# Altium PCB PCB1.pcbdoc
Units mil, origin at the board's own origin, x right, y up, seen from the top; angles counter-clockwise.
Board outline 4550 x 4255 mil, 4 copper layers (Top Layer, Inner1, Inner2, Bottom Layer); 26 components, 17 nets, 63 pads, 18 vias.
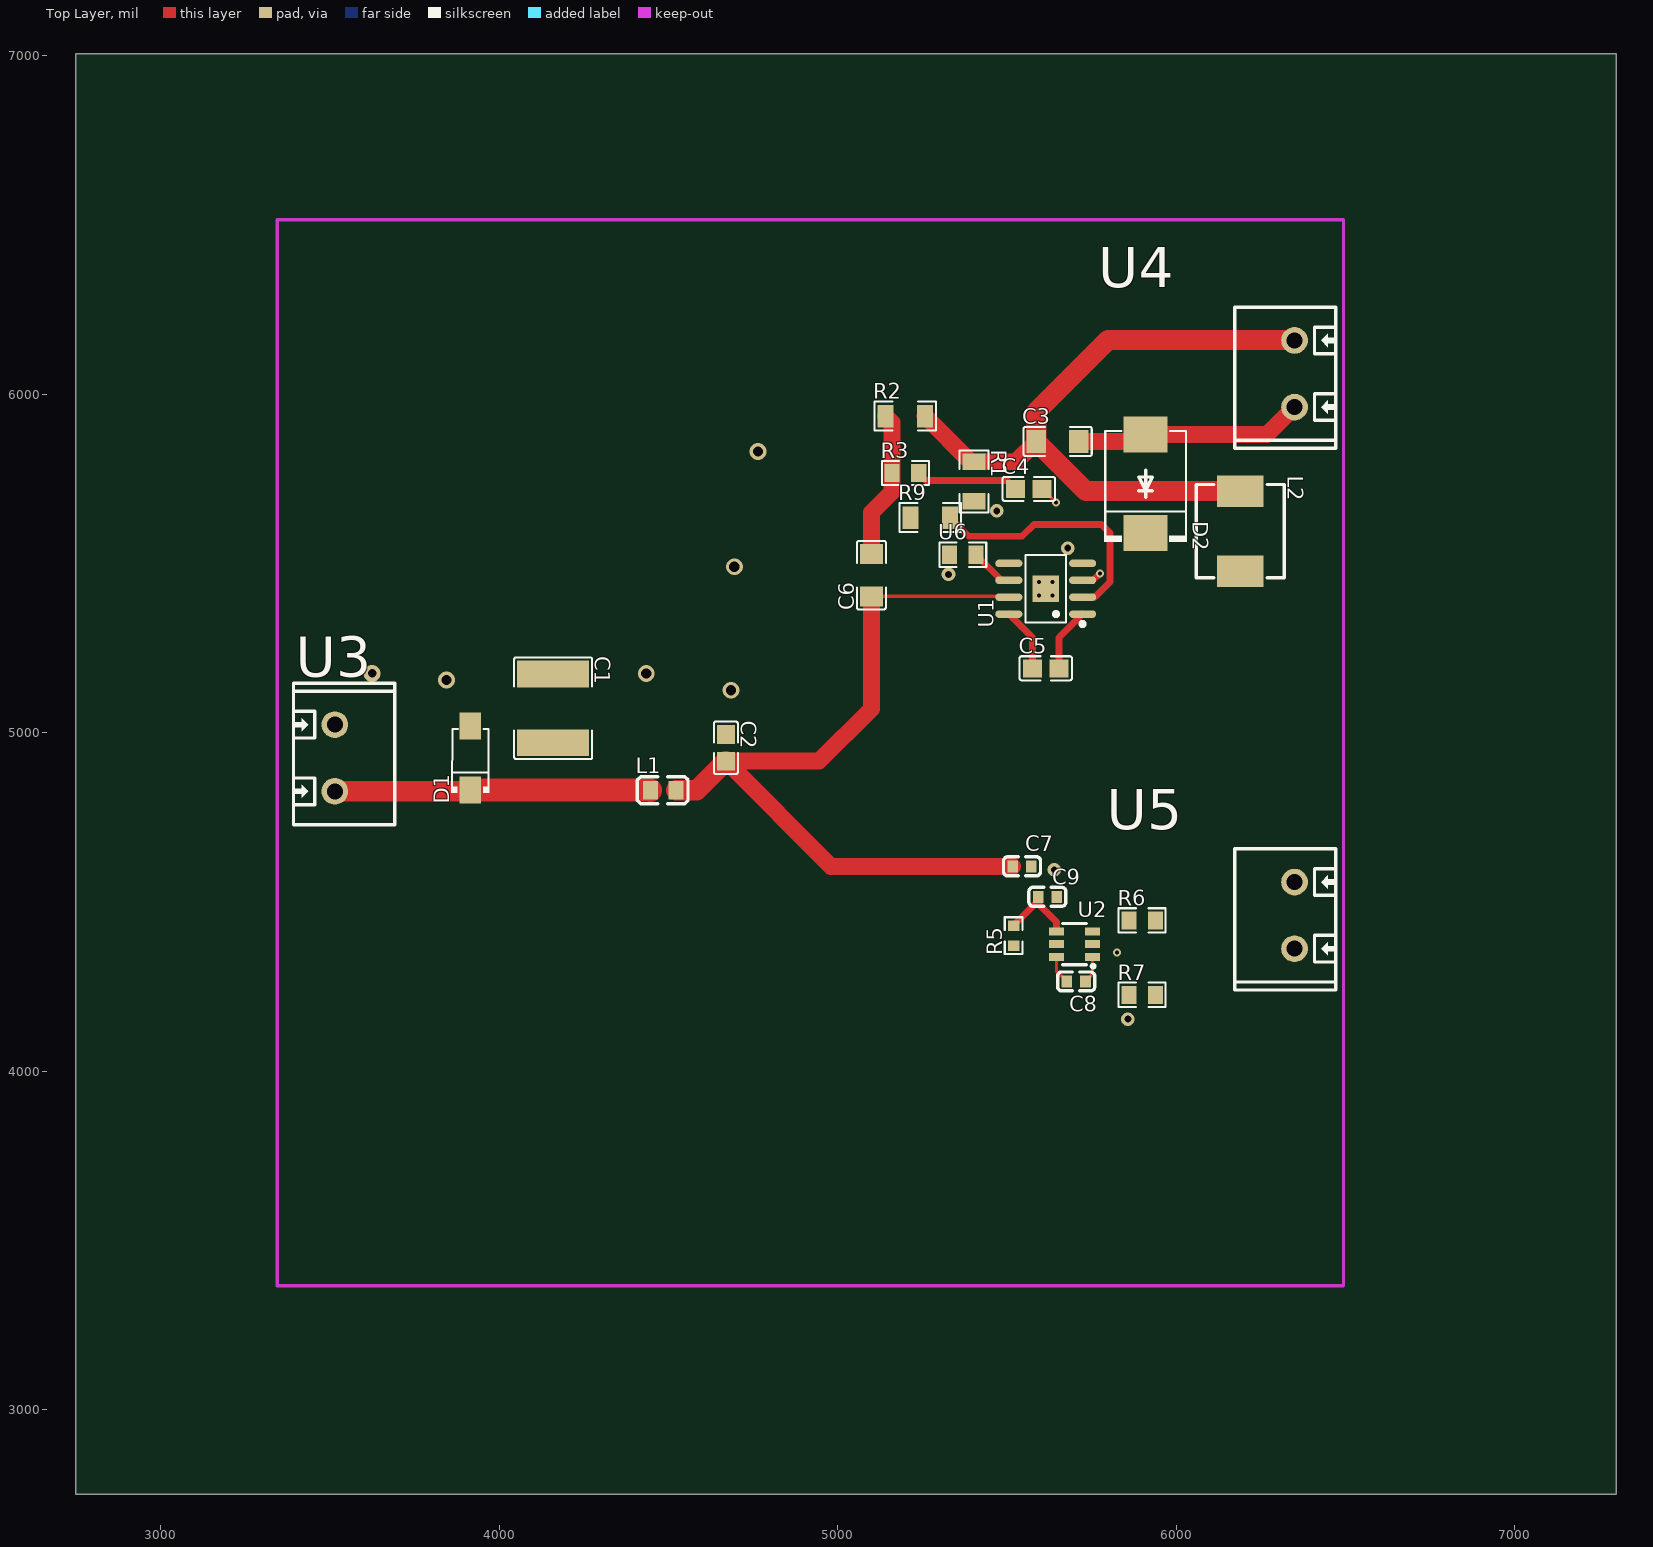
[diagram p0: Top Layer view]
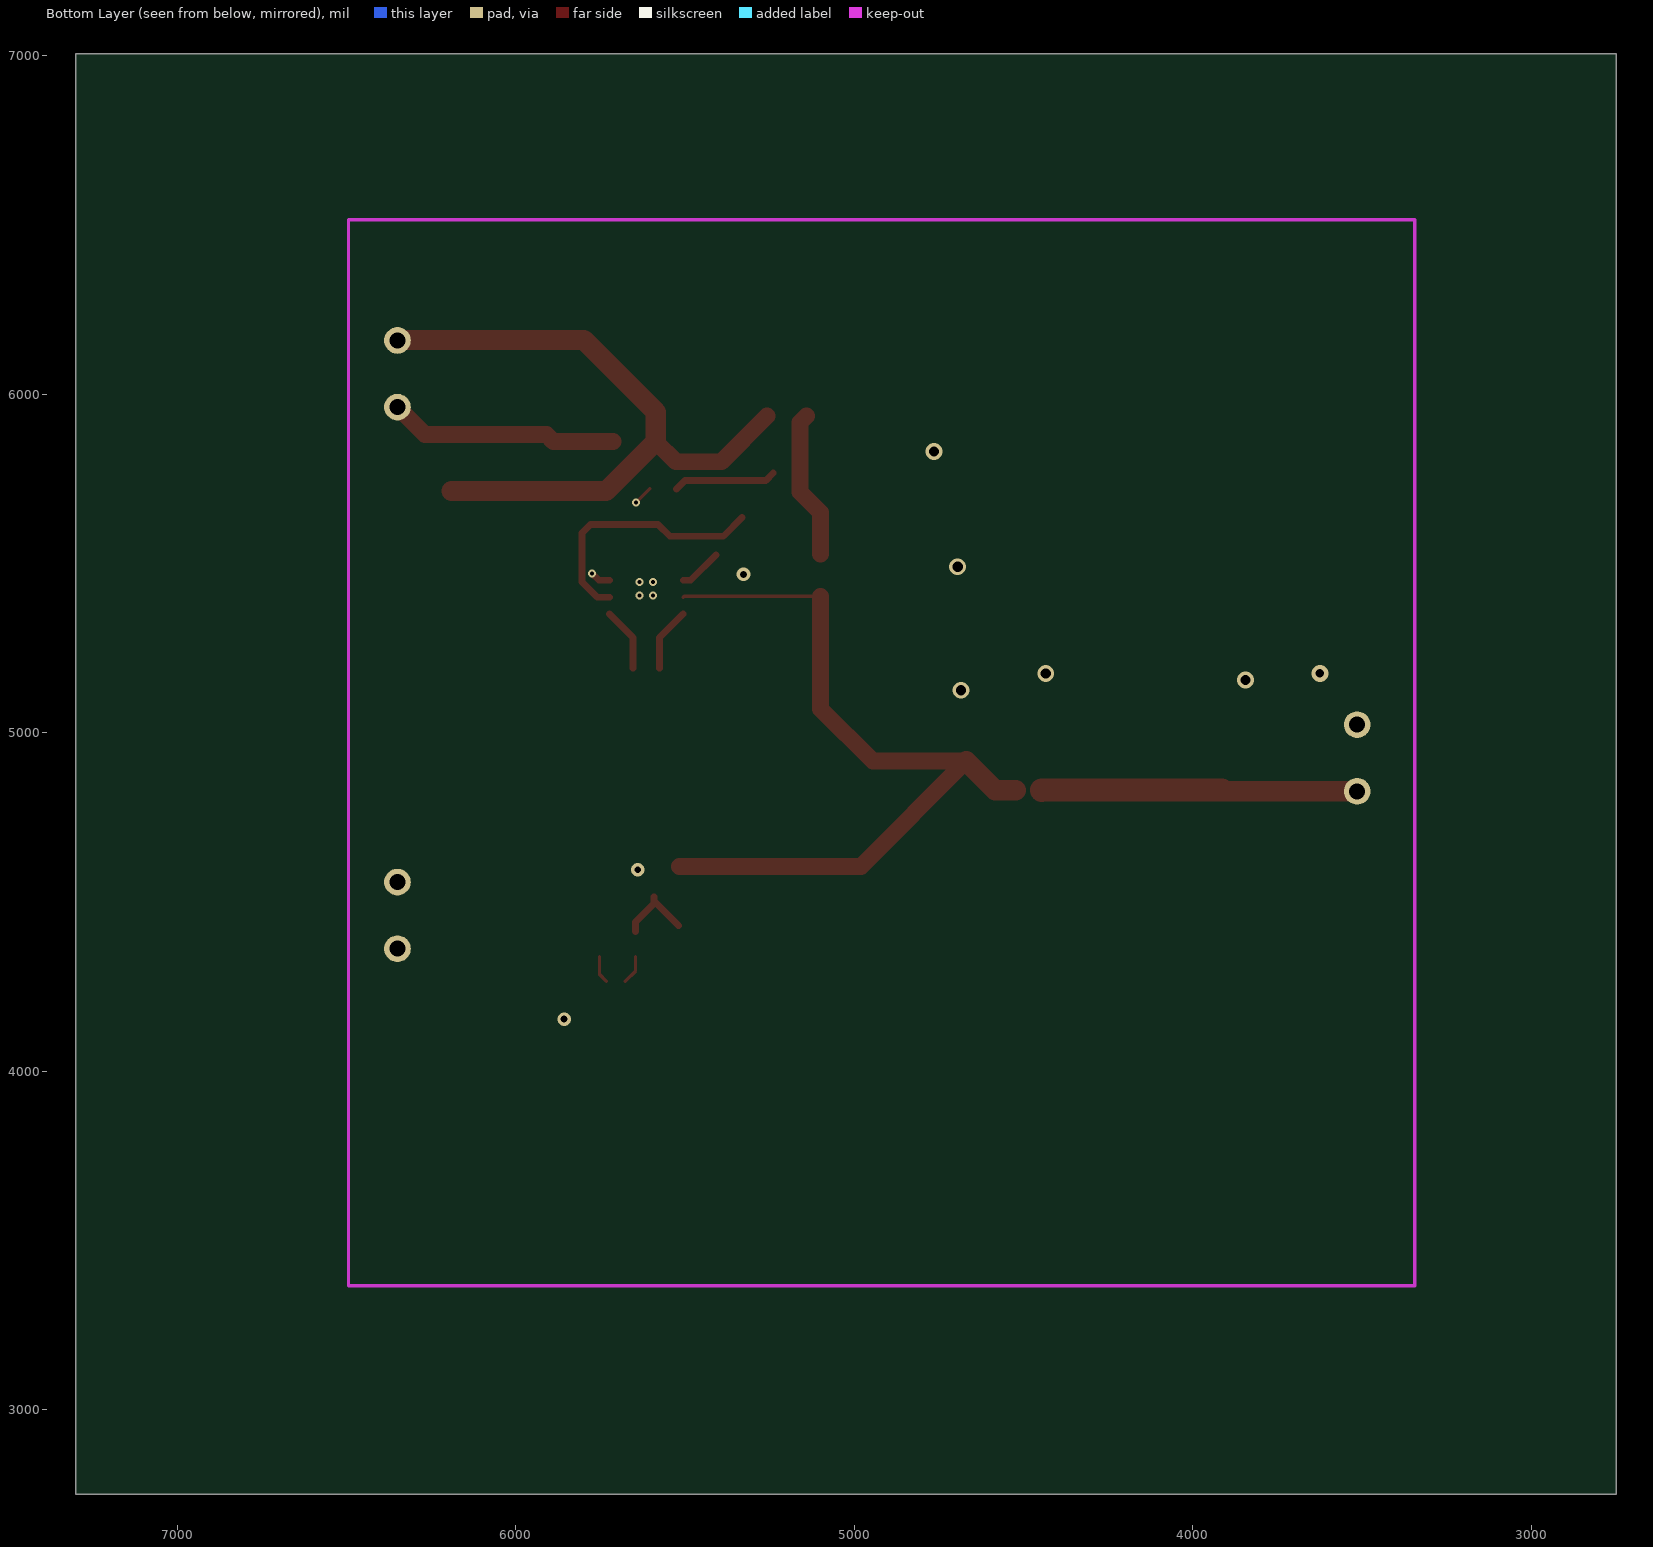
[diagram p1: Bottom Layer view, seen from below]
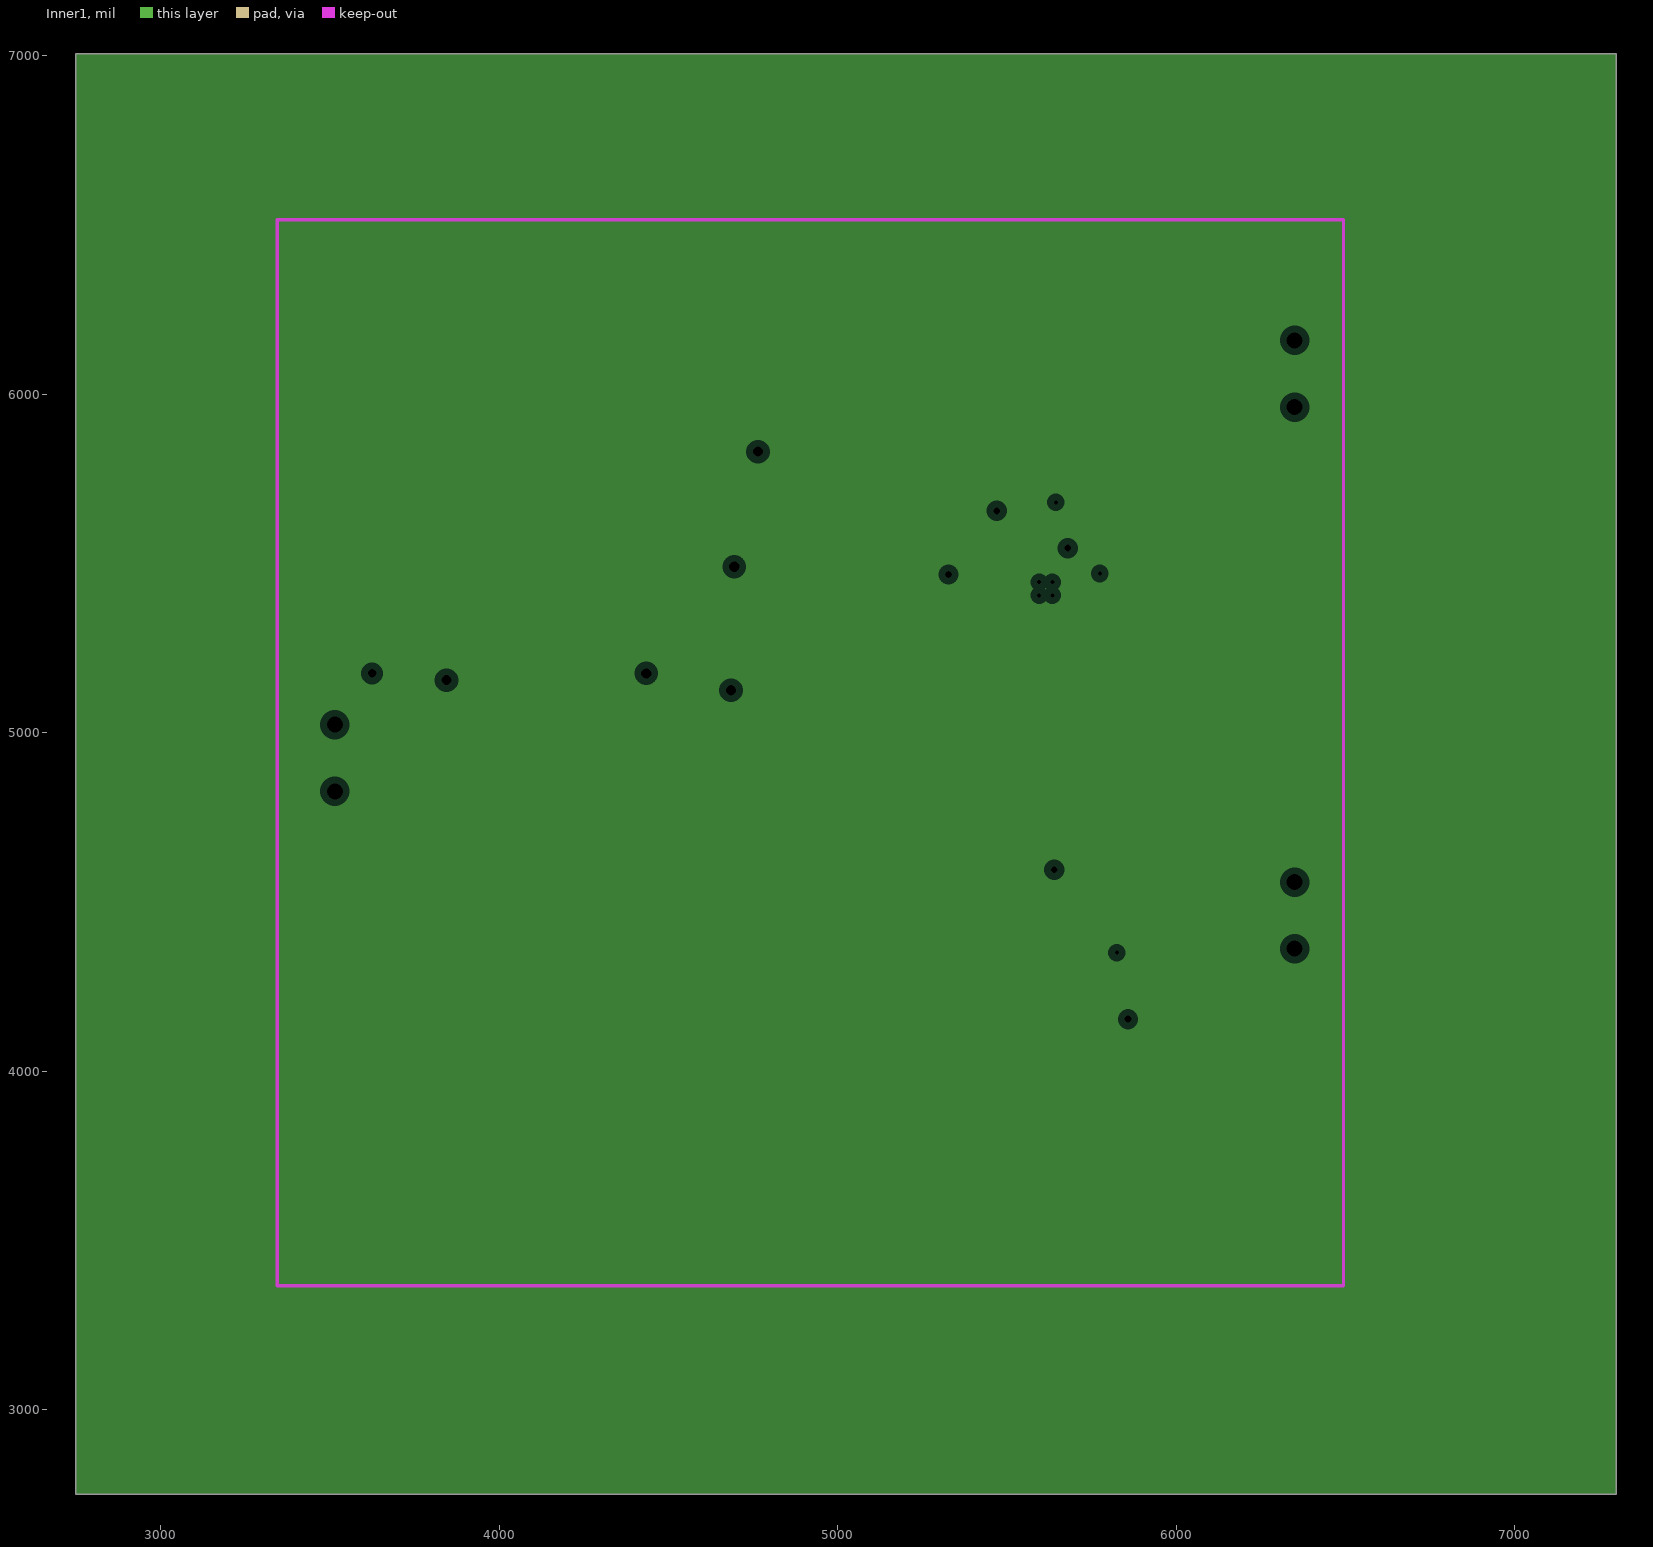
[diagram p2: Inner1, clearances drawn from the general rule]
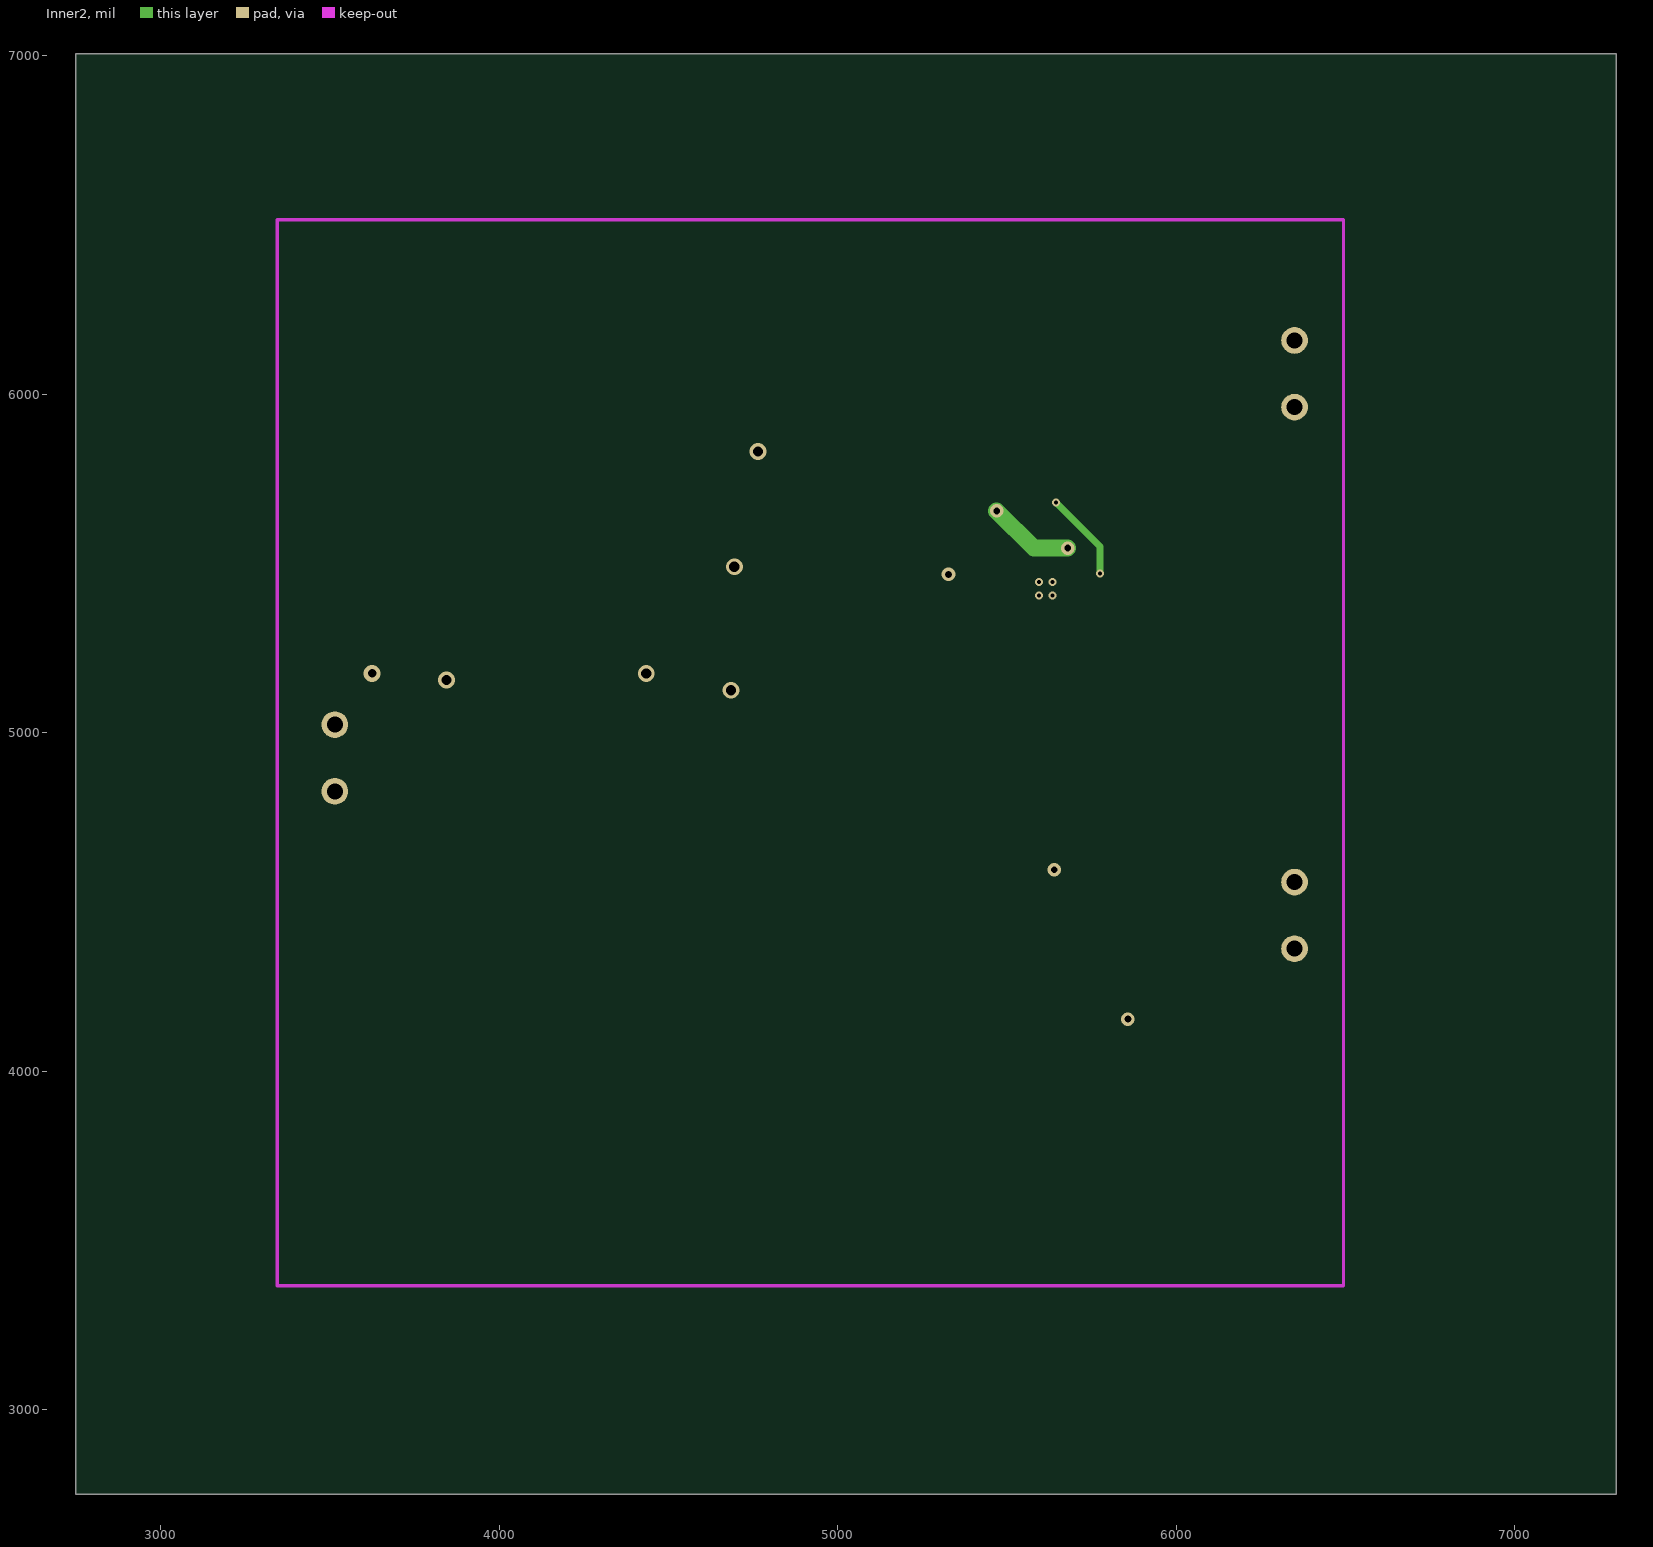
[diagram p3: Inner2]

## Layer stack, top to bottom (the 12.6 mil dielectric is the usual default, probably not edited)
Top Layer: signal copper (thickness not stored)
Dielectric: dielectric 12.6, FR-4, Dk 4.8
Inner1: plane copper (thickness not stored)
Dielectric: dielectric 12.6, FR-4, Dk 4.8
Inner2: signal copper (thickness not stored)
Dielectric: dielectric 12.6, FR-4, Dk 4.8
Bottom Layer: signal copper (thickness not stored)

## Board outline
7300,2750 2750,2750 2750,7005 7300,7005

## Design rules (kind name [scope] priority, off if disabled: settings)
BoardOutlineClearance copperThickness1oz [All] p0: genericclearance=10 ignorepadtopadclearanceinfootprint=FALSE except(0: Arc-SplitContinuation Track-SplitContinuation SMDPad-SplitContinuation THPad-SplitContinuation Via-SplitContinuation Fill-SplitContinuation Poly-SplitContinuation Region-SplitContinuation Text-SplitContinuation; 6: Track-CutoutEdge SMDPad-CutoutEdge THPad-CutoutEdge Via-CutoutEdge Region-CutoutEdge; 11.8: Track-OutlineEdge SMDPad-OutlineEdge THPad-OutlineEdge Via-OutlineEdge Fill-OutlineEdge Region-OutlineEdge Poly-OutlineEdge Text-OutlineEdge Fill-CutoutEdge)
BoardOutlineClearance copperThickness2oz [All] p0: genericclearance=10 ignorepadtopadclearanceinfootprint=FALSE except(0: Arc-SplitContinuation Track-SplitContinuation SMDPad-SplitContinuation THPad-SplitContinuation Via-SplitContinuation Fill-SplitContinuation Poly-SplitContinuation Region-SplitContinuation Text-SplitContinuation; 6: Track-CutoutEdge SMDPad-CutoutEdge THPad-CutoutEdge Via-CutoutEdge Region-CutoutEdge; 11.8: Track-OutlineEdge SMDPad-OutlineEdge THPad-OutlineEdge Via-OutlineEdge Fill-OutlineEdge Region-OutlineEdge Poly-OutlineEdge Text-OutlineEdge Fill-CutoutEdge)
Clearance copperThickness1oz [(InNet('$1N4446') OR InNet('AGND') OR InNet('VIN') OR InNet('GND') OR InNet('$1N1324') OR InNet('$1N1769') OR InNet('$1N1774') OR InNet('$1N1127') OR InNet('$1N1858') OR InNet('$1N3009') OR InNet('$1N3020') OR InNet('$1N3287') OR InNet('$1N1436') OR InNet('$1N3600') OR InNet('$1N3416') OR InNet('$1N4826') OR InNet('$1N1958'))] p1: gap=7 ignorepadtopadclearanceinfootprint=FALSE except(4: Track-Track; 6: Track-SMDPad SMDPad-SMDPad Track-THPad SMDPad-THPad THPad-THPad Track-Via SMDPad-Via THPad-Via Via-Via SMDPad-Fill THPad-Fill Via-Fill Fill-Fill Track-Region SMDPad-Region THPad-Region Via-Region Region-Region Track-Poly SMDPad-Poly THPad-Poly Via-Poly Fill-Poly Region-Poly Poly-Poly Track-Text SMDPad-Text THPad-Text Via-Text Fill-Text Region-Text Poly-Text Text-Text; 6.9: Track-Hole SMDPad-Hole THPad-Hole Via-Hole Fill-Hole Region-Hole Poly-Hole Text-Hole Sheet-Hole; 11.8: Track-Fill Fill-Region Track-Sheet SMDPad-Sheet THPad-Sheet Via-Sheet Fill-Sheet Region-Sheet Poly-Sheet Text-Sheet)
Clearance copperThickness2oz [All] p1: gap=7 ignorepadtopadclearanceinfootprint=FALSE except(6: Track-SMDPad SMDPad-SMDPad Track-THPad SMDPad-THPad THPad-THPad Track-Via SMDPad-Via THPad-Via Via-Via SMDPad-Fill THPad-Fill Via-Fill Fill-Fill Track-Region SMDPad-Region THPad-Region Via-Region Region-Region Track-Poly SMDPad-Poly THPad-Poly Via-Poly Fill-Poly Region-Poly Poly-Poly Track-Text SMDPad-Text THPad-Text Via-Text Fill-Text Region-Text Poly-Text Text-Text; 6.9: Track-Hole SMDPad-Hole THPad-Hole Via-Hole Fill-Hole Region-Hole Poly-Hole Text-Hole Sheet-Hole; 8: Track-Track; 11.8: Track-Fill Fill-Region Track-Sheet SMDPad-Sheet THPad-Sheet Via-Sheet Fill-Sheet Region-Sheet Poly-Sheet Text-Sheet)
DiffPairsRouting differentialPair [All] p1: maxuncoupledlength=10 minlimit=6 maxlimit=6 mostfreqgap=6 toplayer_minwidth=5 toplayer_prefwidth=10 toplayer_maxwidth=100 bottomlayer_minwidth=5 bottomlayer_prefwidth=10 bottomlayer_maxwidth=100 midlayer2_minwidth=5 midlayer2_prefwidth=10 midlayer2_maxwidth=100
PasteMaskExpansion pasteMaskExpansion [All] p1: expansion=0
PlaneConnect innerPlane [All] p1: planeconnectstyle=Relief reliefexpansion=20 reliefentries=4 reliefconductorwidth=10 reliefairgap=10
PolygonConnect copperRegion [All] p1: connectstyle=Relief reliefentries=4 reliefconductorwidth=30 polygonreliefangle="90 Angle" airgapwidth=10
PolygonConnect copperRegion1 [All] p1: connectstyle=Direct reliefentries=4 reliefconductorwidth=10 polygonreliefangle="90 Angle" airgapwidth=10
RoutingVias viaSize [All] p1: viastyle="Through Hole" holewidth=12 minholewidth=11.8 maxholewidth=248 width=24 minwidth=19.7 maxwidth=393.7
SolderMaskExpansion solderMaskExpansion [All] p1: useseparateexpansions=TRUE expansion=2 expansionbottom=2
Width copperThickness1oz [All] p1: maxlimit=100 minlimit=5 preferedwidth=10
Width copperThickness2oz [All] p1: maxlimit=100 minlimit=8 preferedwidth=50

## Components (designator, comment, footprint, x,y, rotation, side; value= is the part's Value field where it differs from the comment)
C1 "FS55X226K500EHG" C2220 4160,5071.84 r270 top
C2 "CL21B105KBFNNNE" C0805 4670,4955 r270 top
C3 "GCM31CR70J226KE23L" C1206 5650,5860 r0 top
C4 "CC0805JRNPO9BN151" C0805 5565,5720 r0 top
C5 "CAP_0805" C0805 5615,5190 r0 top
C6 "HGC1206R5106K500NSPJ" C1206 5100,5465 r90 top
C7 "CL10A226MP8NUNE" C0603 5545,4605 r180 top
C8 "CAP_0603" C0603 5705,4265 r0 top
C9 "CAP_0603" C0603 5620,4515 r180 top
D1 "SMAJ15A_C19077535" SMA_L4.3-W2.6-LS5.0-RD 3915,4925 r90 top
D2 "SS34_C154551" SMC_L6.9-W5.9-LS7.9-RD 5910,5735 r90 top
L1 "BLM21PG221SN1D" L0805 4485,4830 r0 top
L2 "MWSA0603S-150MT" IND-SMD_L7.3-W6.8 6190,5595 r270 top
R1 "1206W4F2103T5E" R1206 5403.22,5741.78 r270 top
R2 "FRC1206F4022TS" R1206 5200,5935 r0 top
R3 "0805W8F1003T5E" R0805 5200.63,5766.89 r0 top
R5 "Res_0603" R0603 5520,4400 r90 top
R6 "Res_0805" R0805 5900,4445 r0 top
R7 "Res_0805" R0805 5900,4225 r0 top
R9 "Res_1206" R1206 5273.99,5635.16 r0 top
U1 "MP1584EN-LF-Z" SOIC-8_L5.0-W4.0-P1.27-LS6.0-BL-EP2.0 5615,5425 r90 top
U2 "TPS560430YFDBVR" SOT-23-6_L2.9-W1.6-P0.95-LS2.8-BR 5700,4375 r0 top
U3 "DG301-5.0-02P-14-00A(H)" CONN-TH_DEGSON_DG301-5.0-02P 3515,4925 r270 top
U4 "DG301-5.0-02P-14-00A(H)" CONN-TH_DEGSON_DG301-5.0-02P 6350,6060 r90 top
U5 "DG301-5.0-02P-14-00A(H)" CONN-TH_DEGSON_DG301-5.0-02P 6350,4460 r90 top
U6 "FRC0805F2492TS" R0805 5370,5525 r0 top

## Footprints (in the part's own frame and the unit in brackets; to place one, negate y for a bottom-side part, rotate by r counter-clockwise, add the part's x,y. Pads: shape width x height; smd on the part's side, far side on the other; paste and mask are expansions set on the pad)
C0603 [mm]
  rect 0.8x0.9 smd: 1(-0.7,0) 2(0.7,0)
  silkscreen extent -1.39,-0.71 1.39,0.71
C0805 [mm]
  rect 1.41x1.35 smd: 1(-1,0) 2(1,0)
  silkscreen extent -1.96,-0.9 1.96,0.9
C1206 [mm]
  rect 1.485x1.728 smd: 1(-1.593,0) 2(1.593,0)
  silkscreen extent -2.56,-1.09 2.56,1.09
C2220 [mm]
  rect 2.01x5.4 smd: 1(-2.58,0) 2(2.58,0)
  silkscreen extent -3.81,-2.93 3.81,2.93
CONN-TH_DEGSON_DG301-5.0-02P [mm]
  round 2 hole 1.2: 1(-2.5,0) 2(2.5,0)
  silkscreen extent -5.6,-3.1 5,4.5
IND-SMD_L7.3-W6.8 [mm]
  rect 2.35x3.5 smd: 1(-3,0) 2(3,0)
  silkscreen extent -3.5,-3.3 3.5,3.3
L0805 [mil]
  rect 44.59x54.21 smd: 1(-38.04,0) 2(38.04,0)
  silkscreen extent -77,-40 73,40
R0603 [mil]
  rect 31.75x34.02 smd: 1(-29.66,0) 2(29.66,0)
  silkscreen extent -55,-26 55,26
R0805 [mm]
  rect 1.133x1.377 smd: 1(-1,0) 2(1,0)
  silkscreen extent -1.76,-0.92 1.76,0.92
R1206 [mil]
  rect 47.54x66.97 smd: 1(-58.22,0) 2(58.22,0)
  silkscreen extent -91,-42 91,42
SMA_L4.3-W2.6-LS5.0-RD [mm]
  rect 2.046x1.62 smd: 1(-2.404,-0.009) 2(2.404,0.009)
  silkscreen extent -2.61,-1.44 2.16,1.44
SMC_L6.9-W5.9-LS7.9-RD [mm]
  rect 2.7x3.3 smd: 1(-3.686,0) 2(3.686,0)
  silkscreen extent -4.36,-3.1 3.98,3.1
SOIC-8_L5.0-W4.0-P1.27-LS6.0-BL-EP2.0 [mm]
  oval 0.574x2.038 smd: 1(-1.905,-2.769) 2(-0.635,-2.769) 3(0.635,-2.769) 4(1.905,-2.769) 5(1.905,2.769) 6(0.635,2.769) 7(-0.635,2.769) 8(-1.905,2.769)
  rect 2x2 smd: 9(0,0)
  silkscreen extent -2.79,-2.92 2.53,1.52
SOT-23-6_L2.9-W1.6-P0.95-LS2.8-BR [mm]
  rect 1.1x0.6 smd: 1(1.35,-0.95) 2(1.35,0) 3(1.35,0.95) 4(-1.35,0.95) 5(-1.35,0) 6(-1.35,-0.95)
  silkscreen extent -0.9,-1.78 1.52,1.55

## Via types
v1: diameter 24, hole 12, Top Layer to Bottom Layer, 6 vias
v2: diameter 50, hole 30, Top Layer to Bottom Layer, 5 vias
v3: diameter 40, hole 20, Top Layer to Bottom Layer, 3 vias
v4: diameter 40, hole 20, Top Layer to Inner2, 2 vias
v5: diameter 50, hole 25, Top Layer to Bottom Layer, 1 vias
v6: diameter 24, hole 12, Top Layer to Inner1, 1 vias

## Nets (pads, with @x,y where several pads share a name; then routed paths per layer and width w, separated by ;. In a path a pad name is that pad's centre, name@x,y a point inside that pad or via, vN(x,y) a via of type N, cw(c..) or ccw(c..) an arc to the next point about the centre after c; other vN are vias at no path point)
$1N1127: C5.2 D2.1 L2.2 U1.1 | length 188.8
  Top Layer w20: C5.2 5654.37,5280.35 U1.1
$1N1324: C3.1 L2.1 R1.1 R2.2 U4.2 | length 2002.2
  Top Layer w50: R2.2 R1.1@5393.22,5800 ; R1.1 5527.3,5800 C3.1
  Top Layer w59: C3.1 5734.19,5713.11 L2.1
  Top Layer w60: C3.1 5587.3,5947.3 5800,6160 6348.43,6160 U4.2
$1N1436: R1.2 U1.4 | length 255.6
  Inner2 w50: v4(5470,5655) 5580,5545 v4(5680,5545)
$1N1769: C4.2 U1.3 | length 380.3
  Top Layer w10: C4.2 5644.37,5680 v1(5645,5680)
  Top Layer w20: U1.3 5755,5450 v1(5775,5470)
  Inner2 w20: v1(5645,5680) 5775,5550 v1(5775,5470)
$1N1774: C4.1 R3.2 | length 305.1
  Top Layer w20: R3.2 5261.89,5745 5500.63,5745 C4.1
$1N1858: C5.1 U1.8 | length 188.8
  Top Layer w20: U1.8 5575.63,5280.35 C5.1
$1N1958: U1.6 U6.2 | length 127.4
  Top Layer w20: U6.2@5409.37,5524.44 5483.81,5450 U1.6
$1N3009: C8.2 U2.1 | length 81.1
  Top Layer w10: C8.2 5753.15,4285.59 U2.1
$1N3020: C8.1 U2.6 | length 85.3
  Top Layer w10: U2.6 5646.85,4295.59 C8.1
$1N3287: C9.2 R5.2 U2.4 | length 227.6
  Top Layer w20: R5.2 C9.2@5592.44,4502.1 ; C9.2 C9.2@5592.44,4502.1 ; U2.4 5646.85,4440.68 5592.44,4495.09 C9.2@5592.44,4502.1
$1N3416: R6.1 U2.3
$1N3600: R6.2 R7.2 U5.2
$1N4446: C1.2 D1.1 L1.1 U3.2 | length 933.7
  Top Layer w60: U3.2 3911.59,4826.57 D1.1
  Top Layer w69: D1.1 4446.6,4830.35 L1.1
$1N4826: R9.2 U1.2 | length 765.1
  Top Layer w20: R9.2 5387.37,5580 5545,5580 5580,5615 5780,5615 5805,5590 5805,5445 5760,5400 U1.2
AGND: C1.1 C2.1 C3.2 C6.2 C7.1 C9.1 D1.2 D2.2 R2.1 R3.1 R7.1 U3.1 U4.1 U5.1 U6.1 | length 1120.1
  Top Layer w50: C6.2 5100,5650 5161.26,5711.26 R3.1 5161.26,5915.52 R2.1 ; C3.2 5889.87,5860 D2.2 6268.56,5880.13 U4.1
  other v2: 4685,5125 3845,5155 4435,5175 4695,5490 4765,5830
  other v3: 5857.78,4153.64 5640,4595 5327.77,5467.31
  other v5: 3625,5175
GND: U1.5 U1.9 U2.2
  other v1: 5595.31,5405.31 5634.69,5405.31 5595.31,5444.69 5634.69,5444.69
  other v6: 5825,4350
VIN: C2.2 C6.1 C7.2 L1.2 R5.1 R9.1 U1.7 U2.5 | length 2391.7
  Top Layer w10: C6.1 5503.68,5402.3 U1.7
  Top Layer w50: C6.1 5100,5070 4945.63,4915.63 C2.2 4980.63,4605 C7.2
  Top Layer w60: L1.2 4584.37,4830 C2.2

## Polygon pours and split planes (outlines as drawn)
AGND on Bottom Layer (solid, remove dead copper, pour order 44): 3075,6710 7050,6710 7050,3210 3075,3210
GND on Top Layer (solid, remove dead copper, pour order 38): 3105,6690 6765,6690 6765,3000 3105,3000
GND on Top Layer (solid, remove dead copper, pour order 40): 3015,6755 7005,6755 7005,3010 3015,3010
GND on Top Layer (solid, remove dead copper, pour order 42): 3000,6660 6795,6660 6795,3230 3000,3230
$1N4446 on Top Layer (solid, remove dead copper, pour order 0): 4049.65,4990 4000,4940.35 4000,4850 3995,4845 4344.2,4845 4350,4836.74 4350,4940 4300,4990
AGND on Top Layer (solid, remove dead copper, pour order 2): 3415,4936.81 3951.81,4936.81 4070,5055 4385,5055 4490,4950 4820,4950 4850,4980 4850,5280 4750,5380 3415,5380
VIN on Top Layer (solid, remove dead copper, pour order 4): 5100,5402.3 5130,5432.3 5432.7,5432.3 5440,5425 5509.08,5425 5534.08,5400 5510,5375.92 5510,5370 5135,5370 5130,5375 5127.3,5375
$1N1127 on Top Layer (solid, remove dead copper, pour order 6): 5697.08,5350 5722.08,5375 5765,5375 5830,5440 5830,5615 6003.76,5615 6003.76,5353.42 5910,5259.65 5815.35,5259.65 5735,5340 5707.08,5340
VIN on Top Layer (solid, remove dead copper, pour order 8): 5171.69,5635.16 5171.69,5461.69 5146.29,5395 5290.32,5395 5290.32,5444.68 5265,5470 5265,5630 5259.84,5635.16
AGND on Top Layer (solid, remove dead copper, pour order 10): 5300,5555 5360,5555 5360,5442.23 5297.84,5442.23 5297.84,5552.84
$1N1127 on Top Layer (solid, remove dead copper, pour order 12): 5985,5545 6310,5545 6310,5306.15 5950,5306.15 5950,5510
$1N1436 on Top Layer (solid, remove dead copper, pour order 14): 5403.22,5715.09 5464.91,5715.09 5520,5660 5520,5630 5495,5605 5445,5605 5395,5655 5395,5706.87
$1N1436 on Top Layer (solid, remove dead copper, pour order 16): 5645,5585 5665,5565 5715,5565 5765,5515 5765,5485 5687.93,5485 5650,5518.44
AGND on Top Layer (solid, remove dead copper, pour order 18): 5190,5945 5190,5685 5135,5630 5135,5475.73 5004.27,5475.73 5000,5480 4805,5285 4340,5285 4330,5295 4330,6000 4325,6005 5130,6005
AGND on Top Layer (solid, remove dead copper, pour order 20): 4960,5445 4960,5235 4846,5235 4846,5279 4825,5300 4820,5300 4815,5305 4955,5445
VIN on Top Layer (solid, remove dead copper, pour order 22): 5338.43,4605 5365,4578.43 5365,4305.5 5469.5,4305.5 5470,4305 5580.96,4305 5580.96,4389.04 5570,4400 5477.61,4400 5477.61,4467.61 5545,4535 5545,4605
VIN on Top Layer (solid, remove dead copper, pour order 24): 5580,4402.74 5685,4395 5685,4354.76 5580,4335.67
$1N3416 on Top Layer (solid, remove dead copper, pour order 26): 5725,4395 5900,4395 5900,4499.47 5730.53,4499.47 5725,4505
$1N3600 on Top Layer (solid, remove dead copper, pour order 28): 5907.43,4481.11 5907.43,4156.95 5998.05,4156.95 6000,4155 6000,4494.09 5907.43,4494.09
$1N3600 on Top Layer (solid, remove dead copper, pour order 30): 5965,4520 6185,4520 6264.25,4635 6462.85,4635 6462.85,4432.59 6227.59,4432.59 6150,4355 6000.54,4355 5965,4390.54
AGND on Top Layer (solid, remove dead copper, pour order 32): 5570,4660 5570,4550.85 5620,4550.85 5620,4513.82 5646.78,4487.04 5689.69,4487.04 5689.69,4655.31 5685,4660
AGND on Top Layer (solid, remove dead copper, pour order 34): 5860,4285 5805,4285 5805,4115 5810,4110 5878.63,4110 5878.63,4285.85 5860.85,4285.85
GND on Top Layer (solid, remove dead copper, pour order 36): 5720,4390 5855,4390 5855,4321.94 5818.06,4321.94 5785,4355 5725,4355 5720,4360

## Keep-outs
Board Outline Layer:
  lines w10: 3345,3365.39 6494.61,3365.39 6494.61,6515 3345,6515 3345,3365.39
